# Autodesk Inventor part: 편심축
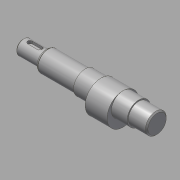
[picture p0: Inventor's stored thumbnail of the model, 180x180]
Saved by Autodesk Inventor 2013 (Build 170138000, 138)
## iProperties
Created: 2017-08
Part Number: 편심축
Material: 강철, 연강
Document SubType Name: Modeling
Designer: mduedu
Density: 1 g/cm^3
Author: mduedu
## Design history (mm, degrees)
sketch "스케치1"
  geometry: L1 (0, 0)-(110, 0); L2 (110, 0)-(110, 8.5); L3 (110, 8.5)-(95, 8.5); L4 (95, 8.5)-(95, 9.5); L5 (95, 9.5)-(51, 9.5); L6 (51, 9.5)-(51, 8.5); L7 (51, 8.5)-(19, 8.5); L8 (19, 8.5)-(19, 6); L9 (19, 6)-(0, 6); L10 (0, 6)-(0, 0)
  constraints: 20 end point, 6 parallel, 2 collinear, 2 perpendicular, 1 horizontal
  dimensions: "d0" = 110 distance of L1.start L1.end; "d1" = 17 diameter of L3 L1; "d2" = 19 diameter of L5 L1; "d3" = 12 diameter of L9 L1; "d4" = 19 distance of L8.end L9.end; "d5" = 15 distance of L2.end L3.end; "d6" = 44 distance of L4.end L5.end
revolve "회전1" sketch "스케치1" stored, may be unused: angle "d7" = 90 deg
node "작업 평면1"
sketch "스케치2"
  geometry: C1 r 9.5 at (0, 0) reference; C2 r 13 at (0, -3.5); 1 further point
  constraints: 1 centre point, 1 tangent, 1 vertical alignment
  dimensions: "d8" = 3.5 distance of point (0, 0) C2.centre
extrude "돌출1" join sketch "스케치2" stored distance "d9" = 18; taper "d10" = 0 deg
chamfer "모따기1" distance "d11" = 1; stored, may be unused: second distance "d12" = 2, angle "d13" = 45 deg
node "작업 평면2"
sketch "스케치3"
  geometry: L1 (3.5, -2)-(-4.5, -2); L2 (-4.5, -2)-(-4.5, 2); L3 (-4.5, 2)-(3.5, 2); L4 (3.5, 2)-(3.5, -2); L5 (9.5, 6)-(9.5, -6) reference; A1 r 2 centre (3.5, 0) between (3.5, -2) and (3.5, 2); A2 r 2 centre (-4.5, 0) between (-4.5, 2) and (-4.5, -2); A3 r 2 centre (3.5, 0) between (3.5, 2) and (3.5, -2); A4 r 2 centre (-4.5, 0) between (-4.5, -2) and (-4.5, 2); 1 further point
  constraints: 8 end point, 8 point on circle, 4 centre point, 2 midpoint, 2 parallel, 1 horizontal, 1 horizontal alignment, 1 perpendicular
  dimensions: "d14" = 12 dimension on A2 A1; "d16" = 4 distance between parallel lines of L3 L1; "d17" = 4 distance edge to line of A1 L5
extrude "돌출2" cut sketch "스케치3" distance "d18" = 2.5; taper "d19" = 0 deg
chamfer "모따기2" distance "d20" = 1; stored, may be unused: second distance "d21" = 2, angle "d22" = 45 deg
chamfer "모따기3" distance "d23" = 1; stored, may be unused: second distance "d24" = 2, angle "d25" = 60 deg
fillet "모깎기1" dims "d26" = 0.5
hole "구멍1" diameter "d29" = 3.242; stored, may be unused: countersink angle "d33" = 90 deg, drill point angle "d35" = 118 deg; dims "d30" = 8, "d31" = 4, "d32" = 2, "d34" = 10, "d36" = 10, "d37" = 10
node "솔리드1"
node "절단 모서리 투영1"
